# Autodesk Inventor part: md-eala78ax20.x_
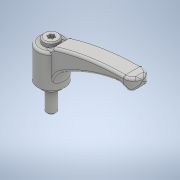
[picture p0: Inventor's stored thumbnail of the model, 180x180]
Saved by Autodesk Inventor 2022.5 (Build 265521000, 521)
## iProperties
Created: 2019-12
Part Number: md-eala78ax20.x_
Material: 一般
Document SubType Name: Modeling
Designer: ImaoCorp
Density: 1 g/cm^3
Appearance: 既定
Sending System: SOLIDWORKS 2018-2018316
MC: AMD64
MC_MODEL: Intel64 Family 6 Model 60 Stepping 3, GenuineIntel
OS: Windows_NT
FRU: Parasolid Version 30.0, build 310,  6- 8-2018
FORMAT: text
GUISE: transmit
KEY: md-eala78ax20
FILE: md-eala78ax20.x_t
DATE: Wed Dec 11 13:12:41 2019
Author: ImaoCorp
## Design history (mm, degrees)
feature "Base1"
node "ソリッド1"
